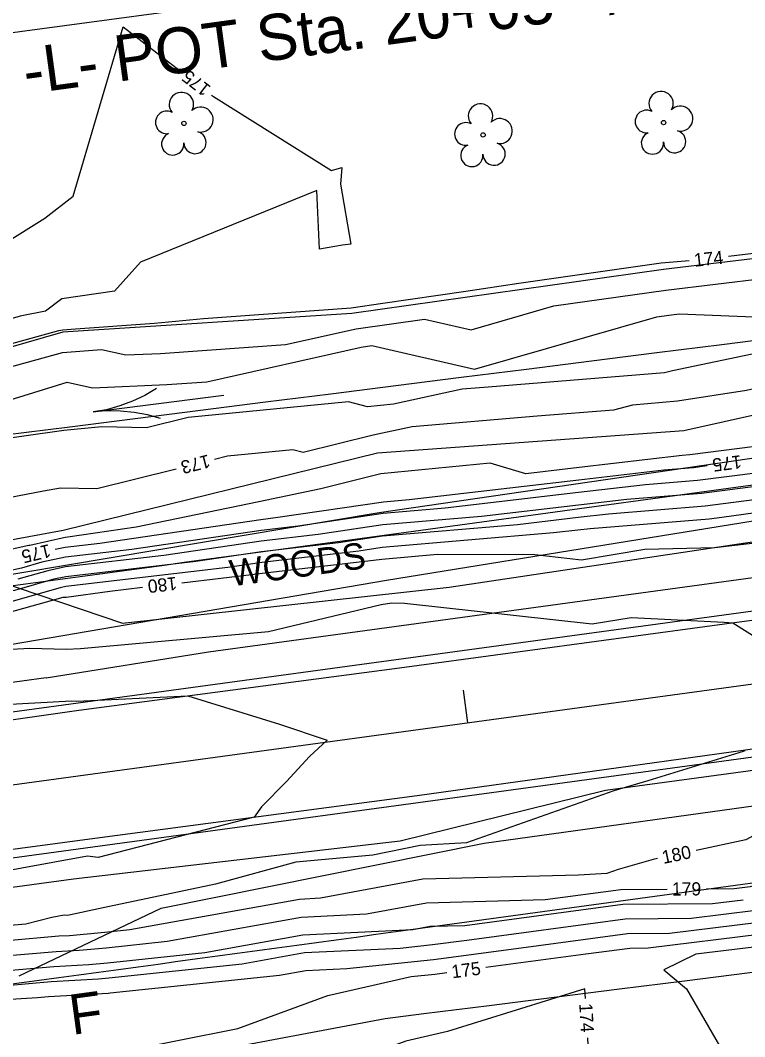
# Model space of a CAD drawing. Extents: x 2086416 to 2115205, y 575507 to 632762.
# Drawn here: x 2112146.4 to 2112256.5, y 581697.5 to 581852.1 of the extents above; entities that cross this region are included whole.
import ezdxf

# ---------------------------------------------------------------- set-up
doc = ezdxf.new("R2010")
doc.units = 0
for name, color, linetype in [('DTM Contours Major', 7, 'Continuous'), ('DTM Contours Major Text', 7, 'Continuous'), ('DTM Contours Minor', 7, 'Continuous'), ('DTM Contours Minor Text', 7, 'Continuous'), ('Exist Hydro River Flow Arrow CELL', 7, 'Continuous'), ('Exist Hydro Stream or Body of Water', 7, 'Continuous'), ('Exist Hydrographic FEMA Cross Section', 7, 'Continuous'), ('Exist Right of Way Line', 7, 'Continuous'), ('Exist Roads EOP', 7, 'Continuous'), ('Exist Vegetation Tree CELL', 7, 'Continuous'), ('Exist Vegetation Woods Line', 7, 'Continuous'), ('Exist Vegetation Woods Line Text', 7, 'Continuous'), ('Prop EOT', 7, 'Continuous'), ('Prop Horizontal Alignment', 7, 'Continuous'), ('Prop Horizontal Alignment Station Label', 7, 'Continuous'), ('Prop Horizontal Alignment Tick Small', 7, 'Continuous'), ('Prop Paved Shoulder', 7, 'Continuous'), ('Prop SS Fill Line', 7, 'Continuous'), ('Prop SS Fill Text', 7, 'Continuous')]:
    doc.layers.add(name, color=color, linetype=linetype)

# ---------------------------------------------------------------- blocks, each defined once
blk = doc.blocks.new('EXIST VEGETATION TREE')
at = {"layer": 'Exist Vegetation Tree CELL'}
blk.add_line((0, 0), (0, 0), dxfattribs=at)
blk.add_circle((0, 0), 0.00652, dxfattribs=at)
for centre, radius, start, end in [((-0.0077, 0.0575), 0.0371, 330.1651, 219.7134), ((-0.0521, 0.0031), 0.0345, 62.6636, 279.3457), ((0.051, 0.0118), 0.038, 257.1011, 134.1999), ((0.0335, -0.058), 0.034, 181.2822, 74.56), ((-0.0341, -0.0624), 0.0338, 111.5671, 6.231)]:
    blk.add_arc(centre, radius, start, end, dxfattribs=at)

msp = doc.modelspace()

# ---------------------------------------------------------------- linework, layer by layer
at = {"layer": 'DTM Contours Major'}
for points in [[(2112112.85, 581797.04), (2112110.37, 581796.22), (2112111.94, 581797.57), (2112111.83, 581802.43), (2112112.4, 581806.66), (2112118.49, 581811.14), (2112122.54, 581808.76), (2112130.66, 581811.84), (2112143.86, 581818.08), (2112150.13, 581821.98), (2112154.41, 581825.32), (2112162.03, 581851.09), (2112170.71, 581844.39)], [(2112175.46, 581840.72), (2112175.77, 581840.48), (2112193.69, 581829.27), (2112195.28, 581829.69), (2112195.05, 581827.16), (2112196.62, 581818.04), (2112195.37, 581817.87), (2112191.9, 581817.27), (2112191.46, 581826.23), (2112164.65, 581815.31), (2112160.7, 581810.9), (2112152.68, 581809.75), (2112150.22, 581807.86), (2112146.34, 581807.07), (2112145.13, 581806.73)], [(2112250.84, 581784.31), (2112248.78, 581784.05), (2112244.24, 581783.68), (2112231.32, 581782.17), (2112205.51, 581779.15), (2112201.62, 581778.82), (2112185.54, 581776.45), (2112182.95, 581776.14), (2112158.47, 581772.54), (2112153.21, 581771.93), (2112151.68, 581771.59)], [(2112170.92, 581766.56), (2112182.79, 581767.95), (2112183.14, 581768), (2112200.95, 581770.1), (2112201.36, 581770.16), (2112209.82, 581770.88), (2112224.63, 581770.84), (2112231.7, 581770.05), (2112241.36, 581771.64), (2112251.99, 581771.89), (2112261.14, 581772.97), (2112270.4, 581772.14)], [(2112107.27, 581718.41), (2112107.01, 581720.41), (2112104.17, 581741.71), (2112103.67, 581744.93), (2112103.37, 581747.12), (2112103.58, 581747.17), (2112103.75, 581747.19), (2112103.84, 581746.71), (2112104.34, 581748.1), (2112105.63, 581751.76), (2112105.89, 581751.76), (2112105.96, 581751.16), (2112105.76, 581750.29), (2112105.48, 581749.34), (2112113.38, 581753.21), (2112114.64, 581753.67), (2112116.47, 581754.51), (2112142.49, 581761.56), (2112144.37, 581761.97), (2112152.89, 581764.37), (2112153.33, 581764.36), (2112159.99, 581765.28), (2112164.96, 581765.86)], [(2112345.09, 581752.91), (2112338.77, 581751.18), (2112335.2, 581750.82), (2112325.17, 581747.75), (2112306.17, 581742.77), (2112300.63, 581741.22), (2112286.12, 581737.9), (2112272.37, 581734.23), (2112262.47, 581730.57), (2112256.74, 581727.43), (2112249.14, 581725.84)], [(2112217.18, 581708.07), (2112232.37, 581710.09), (2112239.06, 581710.99), (2112241.84, 581711.01), (2112259.13, 581713.15), (2112285.07, 581719.83), (2112288.14, 581720.65), (2112307.38, 581725.58), (2112307.75, 581725.68), (2112315.15, 581726.96)], [(2112243.26, 581724.61), (2112242.64, 581724.48), (2112237.31, 581722.95), (2112235.6, 581722.34), (2112231.27, 581722.09), (2112207.57, 581721.48), (2112192.01, 581718.56), (2112188.85, 581718.4), (2112163.04, 581713.74), (2112159.25, 581713.34), (2112153.84, 581712.87), (2112152.23, 581712.78), (2112144.38, 581712.11)], [(2112115.35, 581698.13), (2112120.53, 581693.14), (2112134.17, 581691.59), (2112156.79, 581693.38), (2112161.11, 581695.13), (2112179.46, 581698.78), (2112193.13, 581703.79), (2112205.82, 581706.66), (2112209.41, 581707.04), (2112211.23, 581707.28)]]:
    msp.add_lwpolyline(points, dxfattribs=at)
at = {"layer": 'DTM Contours Minor'}
for points in [[(2112254.07, 581816.2), (2112270.16, 581818.14), (2112276.22, 581818.7), (2112299.96, 581821.57), (2112307.56, 581822.62), (2112329.58, 581826.32), (2112343.62, 581828.68), (2112345.41, 581828.91), (2112345.86, 581828.8), (2112351.13, 581828.16), (2112351.3, 581828.82), (2112352.42, 581829.9), (2112349.84, 581834.07), (2112347.16, 581839.69), (2112345.41, 581840.74), (2112341.86, 581842.42), (2112341.8, 581842.53), (2112336.33, 581854.64), (2112337.93, 581854.53), (2112361.72, 581877.6), (2112365.19, 581879.81), (2112375.59, 581882.41), (2112386.63, 581894.46), (2112387.61, 581897.62)], [(2112125.49, 581797.5), (2112152.23, 581804.9), (2112152.82, 581805.02), (2112154.77, 581805.19), (2112166.81, 581806.03), (2112174.22, 581806.74), (2112196.69, 581808.35), (2112201.53, 581809.07), (2112214.14, 581810.88), (2112222.21, 581812.09), (2112243.84, 581815.18), (2112248.1, 581815.55)], [(2112140.05, 581798.05), (2112152.79, 581801.59), (2112158.72, 581802), (2112162.44, 581801.2), (2112167.71, 581801.43), (2112186.73, 581802.78), (2112197.47, 581805.18), (2112207.84, 581806.65), (2112214.93, 581805.03), (2112227.54, 581808.64), (2112244.57, 581811.06), (2112259.65, 581812.88)], [(2112365.59, 581810.56), (2112361.46, 581809.99), (2112349.02, 581802.57), (2112347.6, 581803.55), (2112345.98, 581804.33), (2112345.2, 581809.49), (2112337.86, 581808.33), (2112330.84, 581808.1), (2112319.28, 581806.42), (2112300.97, 581805.74), (2112300.63, 581804.2), (2112288.06, 581801.33), (2112274.47, 581799.88), (2112256.84, 581795.79), (2112246.32, 581794.17), (2112239.46, 581793.57), (2112236.58, 581792.82), (2112224.97, 581791.88), (2112205.98, 581790.26), (2112200.06, 581788.98), (2112189.4, 581786.34), (2112187.84, 581786.74), (2112177.91, 581785.78), (2112175.91, 581785.28)], [(2112153.01, 581789.68), (2112135.42, 581787.2), (2112127.57, 581785.69), (2112124.67, 581785.16), (2112123.77, 581785.18), (2112111.09, 581783.73), (2112111.04, 581783.78), (2112109.4, 581784.14), (2112111.05, 581784.24), (2112117.07, 581788.12), (2112125.24, 581787.88), (2112134.65, 581791.21), (2112153.51, 581797.04), (2112157.38, 581796.21), (2112168.64, 581796.7), (2112174.72, 581797.13), (2112198.24, 581802.38), (2112199.85, 581802.61), (2112215.46, 581799.05), (2112243.2, 581806.99), (2112245.03, 581807.25), (2112246.64, 581807.45), (2112260.42, 581806.87)], [(2112279.92, 581804.94), (2112272.03, 581804.1), (2112268.77, 581803.34), (2112262.98, 581802.45), (2112245.58, 581798.79), (2112244.37, 581798.47), (2112217.55, 581796.31), (2112213.6, 581795.97), (2112203.11, 581793.7), (2112199.17, 581793.32), (2112196.28, 581794.07), (2112171.9, 581791.7), (2112165.55, 581790.12), (2112158.77, 581790.25), (2112153.01, 581789.68)], [(2112277.59, 581789.77), (2112248.2, 581786), (2112247.04, 581785.9), (2112231.35, 581784.07), (2112223.26, 581783.13), (2112217.82, 581784.76), (2112201.19, 581783.13), (2112192.06, 581780.85), (2112182.63, 581778.88), (2112164.02, 581774.99), (2112153.6, 581773.46), (2112153.19, 581773.42), (2112147.81, 581772.24), (2112147.68, 581772.2), (2112118.86, 581765.87), (2112118.38, 581765.74), (2112114.81, 581764.1), (2112110.37, 581762.54), (2112109.22, 581761.56), (2112106.53, 581760.03), (2112104.59, 581757.38), (2112103.76, 581755.94), (2112103.4, 581754.72)], [(2112307.14, 581785.74), (2112301.4, 581785.1), (2112285.9, 581782.95), (2112280.27, 581782.23), (2112257.98, 581779.14), (2112250.54, 581778.19), (2112235.84, 581776.99), (2112231.22, 581776.45), (2112221.99, 581775.38), (2112201.46, 581773.62), (2112194.79, 581772.64), (2112183.06, 581771.26), (2112173.06, 581769.79), (2112153.28, 581767.47), (2112151.5, 581767.08), (2112145.47, 581765.38), (2112134.61, 581762.99), (2112117.11, 581758.25), (2112113.21, 581756.47), (2112110.52, 581755.49), (2112110.04, 581755.26)], [(2112319.86, 581781.6), (2112316.74, 581781.97), (2112303.89, 581783.45), (2112301.36, 581783.17), (2112281.8, 581780.46), (2112280.88, 581780.34), (2112253.08, 581776.49), (2112251.12, 581776.23), (2112233.04, 581774.76), (2112231.19, 581774.55), (2112227.48, 581774.12), (2112201.41, 581771.89), (2112197.87, 581771.37), (2112183.1, 581769.63), (2112177.92, 581768.87), (2112153.31, 581765.99), (2112152.43, 581765.79), (2112144.92, 581763.67), (2112138.55, 581762.27), (2112122.07, 581757.81)], [(2112258.58, 581783.27), (2112249.37, 581782.09), (2112241.44, 581781.45), (2112231.28, 581780.26), (2112211, 581777.89), (2112201.57, 581777.09), (2112188.62, 581775.18), (2112182.99, 581774.51), (2112163.33, 581771.63), (2112153.23, 581770.44), (2112149.66, 581769.66), (2112146.57, 581768.79), (2112126.74, 581764.43)], [(2112170.08, 581783.83), (2112158.03, 581780.84), (2112152.5, 581780.95), (2112149.88, 581780.47), (2112139.56, 581778.48)], [(2112262.88, 581781.8), (2112249.95, 581780.14), (2112238.64, 581779.22), (2112231.25, 581778.36), (2112216.5, 581776.63), (2112201.52, 581775.36), (2112191.7, 581773.91), (2112183.03, 581772.89), (2112168.2, 581770.71), (2112153.26, 581768.96), (2112150.58, 581768.37), (2112146.02, 581767.08)], [(2112250.74, 581720.01), (2112254.93, 581720.04), (2112257.35, 581720.34), (2112260.97, 581721.27), (2112286.33, 581728.08), (2112286.89, 581728.23), (2112292.96, 581729.86), (2112307.13, 581734.88), (2112324.83, 581738.59), (2112336.35, 581742.12), (2112347.41, 581743.23), (2112355.3, 581744.88), (2112362.61, 581746.71), (2112384.7, 581753.42), (2112397.37, 581755.37), (2112404.55, 581756.78), (2112421.09, 581760.21), (2112433.98, 581763.14), (2112438.11, 581763.77), (2112442.47, 581764.42), (2112445.12, 581764.99)], [(2112141.31, 581756.25), (2112147.82, 581756.6), (2112153.34, 581756.45), (2112155.54, 581756.55), (2112184.12, 581759.16), (2112201.27, 581763.26), (2112202.87, 581763.48), (2112204.81, 581763.47), (2112233.33, 581760.28), (2112239.28, 581761.26), (2112253.44, 581760.55), (2112254.72, 581760.47), (2112263.46, 581754.98)], [(2112136.42, 581747.62), (2112154.15, 581748.58), (2112154.99, 581748.56), (2112171.83, 581749.35), (2112185.78, 581745.02), (2112193.04, 581742.59), (2112190.36, 581740.14), (2112186.86, 581736.31), (2112183.08, 581732.47), (2112181.93, 581730.91), (2112158.22, 581724.78), (2112156.62, 581724.97), (2112141.27, 581722.17)], [(2112256.55, 581740.97), (2112256.31, 581740.88), (2112241.83, 581736.4), (2112236.65, 581734.91), (2112214.24, 581727), (2112207.18, 581726.59), (2112200.01, 581725.13), (2112188.26, 581724.03), (2112176.05, 581720.73), (2112158.98, 581717.09), (2112153.55, 581715.94), (2112153.06, 581716), (2112151.19, 581715.66), (2112147.21, 581714.61), (2112125.58, 581712.76)], [(2112111.79, 581709.15), (2112114.44, 581705.22), (2112114.54, 581705.29), (2112119.33, 581701.59), (2112120.84, 581701.73), (2112148.97, 581703.46), (2112150.67, 581703.6), (2112159.72, 581704.15), (2112160.03, 581704.17), (2112185.81, 581706.88), (2112189.82, 581707.6), (2112196.01, 581707.9), (2112209.24, 581709.27), (2112223.33, 581711.15), (2112238.71, 581713.22), (2112245.11, 581713.27), (2112258.69, 581714.95), (2112279.05, 581720.19), (2112287.68, 581722.51), (2112302.26, 581726.24), (2112306.11, 581727.28)], [(2112343.34, 581704.65), (2112350.12, 581713.38), (2112332.97, 581725.6), (2112308.89, 581715.82), (2112296.37, 581715.24), (2112275.63, 581707.81), (2112279.07, 581713.44), (2112269.95, 581714.02), (2112259.58, 581711.35), (2112249.1, 581710.06), (2112244.24, 581707.7), (2112247.67, 581704.8), (2112261.26, 581681.31), (2112232.74, 581696.26), (2112232.68, 581697.35)], [(2112106.84, 581721.3), (2112107.15, 581719.08), (2112107.76, 581714.41), (2112107.79, 581714.2), (2112108.28, 581714.06), (2112108.35, 581714.07), (2112108.31, 581714.41), (2112112.12, 581708.77), (2112114.44, 581705.35), (2112114.69, 581705.52), (2112117.25, 581703.53), (2112121.15, 581703.9), (2112144.3, 581705.32), (2112151.06, 581705.9), (2112158.25, 581706.33), (2112159.83, 581706.47), (2112180.12, 581708.59), (2112189.58, 581710.3), (2112204.16, 581711), (2112209.06, 581711.51), (2112214.28, 581712.21), (2112238.37, 581715.45), (2112248.38, 581715.53), (2112258.24, 581716.74)], [(2112134.94, 581709.04), (2112151.84, 581710.48), (2112155.31, 581710.69), (2112159.44, 581711.05), (2112168.73, 581712.03), (2112189.09, 581715.7), (2112199.04, 581716.18), (2112208.14, 581717.89), (2112226.18, 581718.36), (2112237.68, 581719.91), (2112244.74, 581719.96)], [(2112139.62, 581707.18), (2112151.45, 581708.19), (2112156.78, 581708.51), (2112159.64, 581708.76), (2112174.43, 581710.31), (2112189.34, 581713), (2112206.06, 581713.81), (2112208.72, 581714.3), (2112213.98, 581714.44), (2112238.03, 581717.68), (2112251.66, 581717.78), (2112256.29, 581718.35)], [(2112232.33, 581703.34), (2112232.24, 581704.8), (2112211.35, 581698.28), (2112205.02, 581696.84), (2112184.7, 581689.39), (2112179.33, 581672.48), (2112183.71, 581663.85), (2112184.18, 581659.93), (2112183.36, 581652.63), (2112202.94, 581641.22), (2112233.96, 581631.14), (2112236.48, 581627.86), (2112240, 581631.41), (2112272.92, 581654.12), (2112271.45, 581659.3)]]:
    msp.add_lwpolyline(points, dxfattribs=at)
at = {"layer": 'Exist Hydro River Flow Arrow CELL'}
for p, q in [((2112157.48, 581792.53), (2112177.31, 581795.08)), ((2112165.33, 581795.05), (2112163.45, 581794.17)), ((2112167.1, 581796.07), (2112165.33, 581795.05)), ((2112163.45, 581794.17), (2112161.49, 581793.44)), ((2112167.4, 581793.8), (2112167.4, 581793.8)), ((2112159.5, 581792.87), (2112157.48, 581792.53)), ((2112159.52, 581792.72), (2112157.48, 581792.53)), ((2112161.49, 581793.44), (2112159.5, 581792.87)), ((2112161.59, 581792.67), (2112159.52, 581792.72)), ((2112163.67, 581792.46), (2112161.59, 581792.67)), ((2112165.71, 581792.08), (2112163.67, 581792.46)), ((2112167.69, 581791.54), (2112165.71, 581792.08))]:
    msp.add_line(p, q, dxfattribs=at)
at = {"layer": 'Exist Hydro Stream or Body of Water'}
for points in [[(2112100.33, 581748.53), (2112103.12, 581756.42), (2112105.73, 581760.69), (2112110.23, 581763.66), (2112118.22, 581768.14), (2112152.91, 581774.53), (2112200.71, 581786.3), (2112247.28, 581789.73), (2112301.11, 581801.74), (2112342.55, 581803.72), (2112346.94, 581801.46), (2112350.79, 581799.08), (2112399.71, 581802.75), (2112440.35, 581810.49), (2112440.68, 581811.97), (2112437.89, 581820.2), (2112440.3, 581822.2), (2112435.86, 581828.25), (2112435.37, 581831.56), (2112437.98, 581841.01), (2112494.54, 581874.35), (2112499.44, 581880.39)], [(2112300.06, 581820.9), (2112244.2, 581814.19), (2112196.82, 581807.52), (2112152.85, 581804.67), (2112109.7, 581792.23), (2112104.21, 581792.8), (2112102.97, 581795.07), (2112103.48, 581799.48), (2112105.46, 581804.5), (2112110.25, 581813.09), (2112115.72, 581818.03), (2112117.41, 581823.6)]]:
    msp.add_lwpolyline(points, dxfattribs=at)
at = {"layer": 'Exist Hydrographic FEMA Cross Section'}
for points in [[(2112263.01, 581804), (2112253.09, 581802.75), (2112243.18, 581801.5), (2112233.26, 581800.24), (2112223.34, 581798.99), (2112213.43, 581797.74), (2112203.51, 581796.49), (2112193.59, 581795.24), (2112183.68, 581793.99), (2112173.76, 581792.73), (2112163.84, 581791.48), (2112153.93, 581790.23), (2112144.01, 581788.98), (2112134.09, 581787.73), (2112124.18, 581786.48), (2112114.26, 581785.22), (2112109.3, 581784.6), (2112104.34, 581783.97), (2112094.42, 581782.72), (2112084.51, 581781.47), (2112074.59, 581780.22), (2112064.67, 581778.97)], [(2112356.49, 581719.74), (2112346.58, 581718.49), (2112341.62, 581717.86), (2112336.66, 581717.24), (2112326.74, 581715.99), (2112316.82, 581714.73), (2112306.91, 581713.48), (2112296.99, 581712.23), (2112287.07, 581710.98), (2112277.16, 581709.73), (2112267.24, 581708.48), (2112257.32, 581707.22), (2112247.41, 581705.97), (2112237.49, 581704.72), (2112227.57, 581703.47), (2112217.66, 581702.22), (2112207.74, 581700.97), (2112201.88, 581700.22), (2111922.67, 581647.71)]]:
    msp.add_lwpolyline(points, dxfattribs=at)
at = {"layer": 'Exist Right of Way Line'}
for points in [[(2112198.38, 581773.35), (2112400.41, 581800.92)], [(2112206.49, 581713.91), (2112408.52, 581741.48)]]:
    msp.add_lwpolyline(points, dxfattribs=at)
for radius in [86637.25, 86697.25]:
    msp.add_arc((2100483.79, 667614.96), radius, 277.6423877, 277.7710056, dxfattribs=at)
at = {"layer": 'Exist Roads EOP'}
for points in [[(2112106.04, 581730.56), (2112104.78, 581739.98), (2112155.28, 581747.16), (2112204.05, 581753.61), (2112253.47, 581760.3), (2112302.94, 581766.96), (2112352.11, 581773.79), (2112401.72, 581780.29), (2112450.22, 581786.9), (2112499.86, 581793.89), (2112548.73, 581800.82), (2112597.59, 581807.57), (2112647.29, 581814.65)], [(2112106.04, 581730.56), (2112107.32, 581720.97), (2112157.7, 581727.7), (2112206.75, 581734.2), (2112256.3, 581741.08), (2112305.32, 581747.93), (2112354.53, 581754.87), (2112403.99, 581761.61), (2112453.01, 581768.18), (2112502.29, 581774.88), (2112551.21, 581782.05), (2112600.41, 581788.81), (2112649.9, 581795.88)]]:
    msp.add_lwpolyline(points, dxfattribs=at)
at = {"layer": 'Exist Vegetation Woods Line'}
msp.add_lwpolyline([(2112301.36, 581782.95), (2112202.06, 581766.89), (2112123.13, 581753.42), (2112119.41, 581763.53), (2112200.97, 581777.22), (2112301.44, 581791.88), (2112399.2, 581802.76), (2112436.7, 581809.61), (2112455.71, 581861.8)], dxfattribs=at)
at = {"layer": 'Prop EOT'}
for p, q in [((2111430.06, 581649.33), (2112312.03, 581769.69)), ((2111433.04, 581627.53), (2112315, 581747.89))]:
    msp.add_line(p, q, dxfattribs=at)
at = {"layer": 'Prop Horizontal Alignment'}
msp.add_line((2111431.55, 581638.43), (2112404.47, 581771.2), dxfattribs=at)
at = {"layer": 'Prop Horizontal Alignment Station Label'}
msp.add_line((2112135.81, 581848.95), (2112267.87, 581866.97), dxfattribs=at)
at = {"layer": 'Prop Horizontal Alignment Tick Small'}
msp.add_line((2112214.43, 581745.27), (2112213.76, 581750.22), dxfattribs=at)
at = {"layer": 'Prop Paved Shoulder'}
for p, q in [((2112175, 581756.03), (2112283.51, 581770.84)), ((2112150.31, 581752.08), (2112175, 581756.03)), ((2112150.31, 581752.08), (2112119.24, 581747.84)), ((2112235.39, 581735.01), (2112315.27, 581745.91)), ((2112204.15, 581727.29), (2112235.39, 581735.01)), ((2112154.47, 581721.53), (2112204.15, 581727.29)), ((2112123.41, 581717.29), (2112154.47, 581721.53))]:
    msp.add_line(p, q, dxfattribs=at)
at = {"layer": 'Prop SS Fill Line'}
for p, q in [((2112211.62, 581765.87), (2112261.07, 581773.29)), ((2112141.15, 581767.4), (2112161.91, 581760.41)), ((2112161.91, 581760.41), (2112211.62, 581765.87)), ((2112216.94, 581726.92), (2112266.46, 581733.81)), ((2112167.82, 581717.08), (2112216.94, 581726.92)), ((2112146.19, 581706.78), (2112167.82, 581717.08))]:
    msp.add_line(p, q, dxfattribs=at)

# ---------------------------------------------------------------- block references
at = {"layer": 'Exist Vegetation Tree CELL', "xscale": 50, "yscale": 50}
for p in [(2112244.21, 581836.54), (2112171.26, 581836.4), (2112216.75, 581834.65)]:
    msp.add_blockref('EXIST VEGETATION TREE', p, dxfattribs=at)

# ---------------------------------------------------------------- texts
at = {"layer": 'DTM Contours Major Text'}
for s, rotation, p in [('175', 142.3403, (2112175.49, 581841.96)), ('175', 187.3108, (2112255.94, 581785.97)), ('175', 193.3221, (2112150.73, 581772.45)), ('180', 186.6788, (2112170.09, 581767.47)), ('180', 11.8364, (2112244.18, 581723.78)), ('175', 7.5775, (2112212.08, 581706.38))]:
    msp.add_text(s, height=2, rotation=rotation, dxfattribs=at).set_placement(p)
at = {"layer": 'DTM Contours Minor Text'}
for s, rotation, p in [('174', 6.1918, (2112248.93, 581814.6)), ('173', 193.9512, (2112174.96, 581786.08)), ('179', 0.4282, (2112245.47, 581718.97)), ('174', 273.3548, (2112231.37, 581702.55))]:
    msp.add_text(s, height=2, rotation=rotation, dxfattribs=at).set_placement(p)
at = {"layer": 'Exist Vegetation Woods Line Text'}
msp.add_text('WOODS', height=4, rotation=7.771, dxfattribs=at).set_placement((2112178.5, 581765.98))
at = {"layer": 'Prop Horizontal Alignment Station Label'}
msp.add_text('-L- POT Sta. 20+05 +/-  ', height=7, rotation=7.771, dxfattribs=at).set_placement((2112147.27, 581840.84))
at = {"layer": 'Prop SS Fill Text'}
msp.add_text('F', height=6.1, rotation=7.771, dxfattribs=at).set_placement((2112154.26, 581697.78))

doc.saveas('drawing.dxf')
